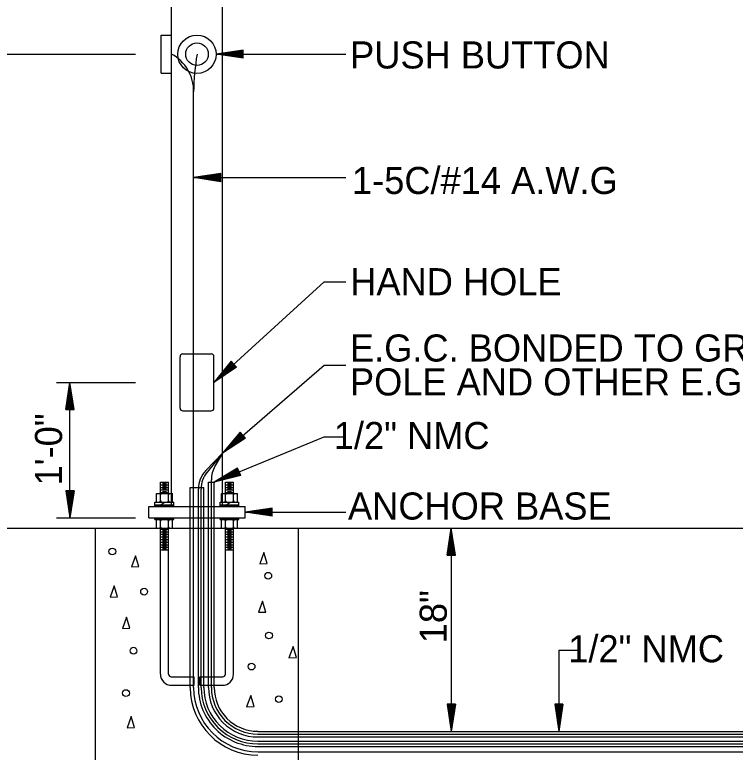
# Model space of a CAD drawing. Extents: x 1370140 to 1371141, y 380020 to 380660.
# Drawn here: x 1370273.3 to 1370406.3, y 380391.4 to 380527.5 of the extents above; entities that cross this region are included whole.
import ezdxf

# ---------------------------------------------------------------- set-up
doc = ezdxf.new("R2010")
doc.units = 0
doc.layers.add('R_Draft', color=7, linetype='Continuous')

msp = doc.modelspace()

# ---------------------------------------------------------------- linework, layer by layer
at = {"layer": 'R_Draft'}
for p, q in [((1370302.28, 380436.73), (1370302.28, 380532.73)), ((1370311.66, 380436.73), (1370311.66, 380532.73)), ((1370300.37, 380523.73), (1370302.28, 380523.73)), ((1370300.37, 380516.73), (1370300.37, 380523.73)), ((1370262.28, 380520.23), (1370295.6, 380520.23)), ((1370315.51, 380520.98), (1370310.51, 380520.23)), ((1370310.51, 380520.23), (1370334.45, 380520.23)), ((1370315.51, 380519.48), (1370310.51, 380520.23)), ((1370315.51, 380520.86), (1370311.35, 380520.23)), ((1370315.51, 380519.61), (1370311.35, 380520.23)), ((1370315.51, 380520.73), (1370312.21, 380520.23)), ((1370315.51, 380519.74), (1370312.21, 380520.23)), ((1370315.51, 380520.61), (1370313.04, 380520.23)), ((1370315.51, 380519.86), (1370313.04, 380520.23)), ((1370315.51, 380520.48), (1370313.89, 380520.23)), ((1370315.51, 380519.99), (1370313.89, 380520.23)), ((1370315.51, 380520.35), (1370314.72, 380520.23)), ((1370315.51, 380520.12), (1370314.72, 380520.23)), ((1370315.51, 380519.48), (1370315.51, 380520.98)), ((1370300.37, 380516.73), (1370302.28, 380516.73)), ((1370306.35, 380403.34), (1370306.35, 380513.28)), ((1370311.35, 380498.2), (1370306.35, 380497.45)), ((1370306.35, 380497.45), (1370334.45, 380497.45)), ((1370311.35, 380496.7), (1370306.35, 380497.45)), ((1370311.35, 380498.08), (1370307.19, 380497.45)), ((1370311.35, 380496.83), (1370307.19, 380497.45)), ((1370311.35, 380497.95), (1370308.05, 380497.45)), ((1370311.35, 380496.95), (1370308.05, 380497.45)), ((1370311.35, 380497.82), (1370308.88, 380497.45)), ((1370311.35, 380497.08), (1370308.88, 380497.45)), ((1370311.35, 380497.7), (1370309.73, 380497.45)), ((1370311.35, 380497.21), (1370309.73, 380497.45)), ((1370311.35, 380497.57), (1370310.56, 380497.45)), ((1370311.35, 380497.33), (1370310.56, 380497.45)), ((1370311.35, 380496.7), (1370311.35, 380498.2)), ((1370310.1, 380459.65), (1370330.44, 380478.2)), ((1370330.44, 380478.2), (1370334.45, 380478.2)), ((1370303.85, 380454.9), (1370303.85, 380464.4)), ((1370304.35, 380464.9), (1370309.6, 380464.9)), ((1370310.1, 380454.9), (1370310.1, 380464.4)), ((1370313.28, 380463.57), (1370310.1, 380459.65)), ((1370313.37, 380463.48), (1370310.71, 380460.21)), ((1370313.45, 380463.39), (1370311.35, 380460.79)), ((1370313.54, 380463.29), (1370311.96, 380461.35)), ((1370313.62, 380463.2), (1370312.59, 380461.92)), ((1370313.71, 380463.11), (1370313.2, 380462.49)), ((1370314.29, 380462.47), (1370313.28, 380463.57)), ((1370314.29, 380462.47), (1370310.1, 380459.65)), ((1370314.21, 380462.56), (1370310.71, 380460.21)), ((1370314.12, 380462.65), (1370311.35, 380460.79)), ((1370311.66, 380446.6), (1370330.44, 380462.85)), ((1370314.04, 380462.74), (1370311.96, 380461.35)), ((1370313.95, 380462.84), (1370312.59, 380461.92)), ((1370313.87, 380462.93), (1370313.2, 380462.49)), ((1370330.44, 380462.85), (1370334.45, 380462.85)), ((1370281.03, 380459.65), (1370295.6, 380459.65)), ((1370282.78, 380454.65), (1370283.53, 380459.65)), ((1370283.53, 380434.65), (1370283.53, 380459.65)), ((1370284.28, 380454.65), (1370283.53, 380459.65)), ((1370282.91, 380454.65), (1370283.53, 380458.81)), ((1370283.04, 380454.65), (1370283.53, 380457.95)), ((1370284.16, 380454.65), (1370283.53, 380458.81)), ((1370284.03, 380454.65), (1370283.53, 380457.95)), ((1370283.16, 380454.65), (1370283.53, 380457.12)), ((1370283.29, 380454.65), (1370283.53, 380456.27)), ((1370283.91, 380454.65), (1370283.53, 380457.12)), ((1370283.78, 380454.65), (1370283.53, 380456.27)), ((1370283.42, 380454.65), (1370283.53, 380455.44)), ((1370283.65, 380454.65), (1370283.53, 380455.44)), ((1370282.78, 380454.65), (1370284.28, 380454.65)), ((1370304.35, 380454.4), (1370309.6, 380454.4)), ((1370310.14, 380441.23), (1370330.44, 380449.6)), ((1370314.93, 380450.46), (1370311.66, 380446.6)), ((1370315.01, 380450.37), (1370312.29, 380447.15)), ((1370315.83, 380449.43), (1370312.29, 380447.15)), ((1370315.09, 380450.27), (1370312.93, 380447.72)), ((1370315.75, 380449.52), (1370312.93, 380447.72)), ((1370315.17, 380450.18), (1370313.56, 380448.27)), ((1370315.67, 380449.62), (1370313.56, 380448.27)), ((1370315.26, 380450.08), (1370314.2, 380448.83)), ((1370315.58, 380449.71), (1370314.2, 380448.83)), ((1370315.34, 380449.99), (1370314.83, 380449.38)), ((1370315.5, 380449.81), (1370314.83, 380449.38)), ((1370315.91, 380449.33), (1370314.93, 380450.46)), ((1370330.44, 380449.6), (1370334.45, 380449.6)), ((1370315.91, 380449.33), (1370311.66, 380446.6)), ((1370311.66, 380446.6), (1370308.61, 380443.4)), ((1370311.66, 380446.6), (1370308.83, 380443.09)), ((1370311.66, 380446.6), (1370310.27, 380444.16)), ((1370314.47, 380443.83), (1370310.14, 380441.23)), ((1370314.52, 380443.71), (1370310.91, 380441.55)), ((1370314.57, 380443.6), (1370311.7, 380441.87)), ((1370314.95, 380442.68), (1370311.7, 380441.87)), ((1370314.62, 380443.48), (1370312.47, 380442.19)), ((1370314.9, 380442.79), (1370312.47, 380442.19)), ((1370314.67, 380443.36), (1370313.26, 380442.52)), ((1370314.85, 380442.91), (1370313.26, 380442.52)), ((1370314.72, 380443.24), (1370314.03, 380442.83)), ((1370314.8, 380443.03), (1370314.03, 380442.83)), ((1370315.05, 380442.44), (1370314.47, 380443.83)), ((1370309.62, 380403.34), (1370309.62, 380441.69)), ((1370315.05, 380442.44), (1370310.14, 380441.23)), ((1370315, 380442.56), (1370310.91, 380441.55)), ((1370300.22, 380441.23), (1370301.72, 380441.23)), ((1370300.22, 380439.15), (1370300.22, 380441.23)), ((1370300.22, 380440.75), (1370301.72, 380440.75)), ((1370300.22, 380440.27), (1370301.72, 380440.27)), ((1370300.6, 380440.98), (1370301.35, 380440.98)), ((1370300.6, 380440.5), (1370301.35, 380440.5)), ((1370300.6, 380440.02), (1370301.35, 380440.02)), ((1370301.72, 380439.15), (1370301.72, 380441.23)), ((1370305.72, 380403.34), (1370305.72, 380440.27)), ((1370305.72, 380440.27), (1370308.22, 380440.27)), ((1370307.22, 380403.34), (1370307.22, 380439.95)), ((1370307.72, 380403.34), (1370307.72, 380439.95)), ((1370308.22, 380403.34), (1370308.22, 380440.27)), ((1370309.1, 380403.34), (1370309.1, 380441.23)), ((1370309.1, 380441.23), (1370310.14, 380441.23)), ((1370310.14, 380403.34), (1370310.14, 380441.23)), ((1370312.22, 380441.23), (1370313.72, 380441.23)), ((1370312.22, 380439.15), (1370312.22, 380441.23)), ((1370312.22, 380440.75), (1370313.72, 380440.75)), ((1370312.22, 380440.27), (1370313.72, 380440.27)), ((1370312.6, 380440.98), (1370313.35, 380440.98)), ((1370312.6, 380440.5), (1370313.35, 380440.5)), ((1370312.6, 380440.02), (1370313.35, 380440.02)), ((1370313.72, 380439.15), (1370313.72, 380441.23)), ((1370282.78, 380439.65), (1370283.53, 380434.65)), ((1370284.28, 380439.65), (1370282.78, 380439.65)), ((1370282.91, 380439.65), (1370283.53, 380435.48)), ((1370283.04, 380439.65), (1370283.53, 380436.34)), ((1370283.16, 380439.65), (1370283.53, 380437.17)), ((1370283.29, 380439.65), (1370283.53, 380438.02)), ((1370283.42, 380439.65), (1370283.53, 380438.86)), ((1370284.28, 380439.65), (1370283.53, 380434.65)), ((1370283.78, 380439.65), (1370283.53, 380438.02)), ((1370284.03, 380439.65), (1370283.53, 380436.34)), ((1370284.16, 380439.65), (1370283.53, 380435.48)), ((1370283.91, 380439.65), (1370283.53, 380437.17)), ((1370283.65, 380439.65), (1370283.53, 380438.86)), ((1370299.47, 380437.57), (1370299.47, 380439.15)), ((1370299.47, 380439.15), (1370302.47, 380439.15)), ((1370300.22, 380439.79), (1370301.72, 380439.79)), ((1370300.22, 380439.31), (1370301.72, 380439.31)), ((1370300.22, 380437.57), (1370300.22, 380439.15)), ((1370300.6, 380439.54), (1370301.35, 380439.54)), ((1370301.72, 380437.57), (1370301.72, 380439.15)), ((1370302.47, 380437.57), (1370302.47, 380439.15)), ((1370311.47, 380437.57), (1370311.47, 380439.15)), ((1370311.47, 380439.15), (1370314.47, 380439.15)), ((1370312.22, 380439.79), (1370313.72, 380439.79)), ((1370312.22, 380439.31), (1370313.72, 380439.31)), ((1370312.22, 380437.57), (1370312.22, 380439.15)), ((1370312.6, 380439.54), (1370313.35, 380439.54)), ((1370313.72, 380437.57), (1370313.72, 380439.15)), ((1370314.47, 380437.57), (1370314.47, 380439.15)), ((1370299.22, 380436.73), (1370299.22, 380437.57)), ((1370299.22, 380437.57), (1370302.72, 380437.57)), ((1370300.22, 380437.06), (1370301.1, 380437.55)), ((1370302.72, 380436.73), (1370302.72, 380437.57)), ((1370311.22, 380436.73), (1370311.22, 380437.57)), ((1370311.22, 380437.57), (1370314.72, 380437.57)), ((1370312.37, 380437.06), (1370313.19, 380437.56)), ((1370314.72, 380436.73), (1370314.72, 380437.57)), ((1370298.1, 380434.65), (1370298.1, 380436.73)), ((1370298.1, 380436.73), (1370315.85, 380436.73)), ((1370299.22, 380437.06), (1370302.72, 380437.06)), ((1370299.22, 380436.89), (1370299.4, 380437.06)), ((1370299.24, 380436.73), (1370299.57, 380437.06)), ((1370299.42, 380436.73), (1370299.75, 380437.06)), ((1370299.59, 380436.73), (1370299.93, 380437.06)), ((1370299.77, 380436.73), (1370300.1, 380437.06)), ((1370299.95, 380436.73), (1370300.22, 380437.01)), ((1370300.12, 380436.73), (1370300.22, 380436.83)), ((1370300.22, 380436.81), (1370300.48, 380437.06)), ((1370300.22, 380436.98), (1370300.3, 380437.06)), ((1370300.32, 380436.73), (1370300.66, 380437.06)), ((1370300.5, 380436.73), (1370300.83, 380437.06)), ((1370300.68, 380436.73), (1370301.01, 380437.06)), ((1370300.85, 380436.73), (1370301.19, 380437.06)), ((1370301.03, 380436.73), (1370301.36, 380437.06)), ((1370301.21, 380436.73), (1370301.54, 380437.06)), ((1370301.38, 380436.73), (1370301.72, 380437.06)), ((1370301.56, 380436.73), (1370301.72, 380436.89)), ((1370301.72, 380436.85), (1370301.93, 380437.06)), ((1370301.72, 380437.03), (1370301.75, 380437.06)), ((1370301.77, 380436.73), (1370302.11, 380437.06)), ((1370301.95, 380436.73), (1370302.28, 380437.06)), ((1370302.13, 380436.73), (1370302.28, 380436.89)), ((1370302.28, 380436.75), (1370302.6, 380437.06)), ((1370302.28, 380436.92), (1370302.42, 380437.06)), ((1370302.44, 380436.73), (1370302.72, 380437.01)), ((1370302.62, 380436.73), (1370302.72, 380436.83)), ((1370311.22, 380437.06), (1370314.72, 380437.06)), ((1370311.26, 380436.73), (1370311.59, 380437.06)), ((1370311.28, 380436.93), (1370311.41, 380437.06)), ((1370311.43, 380436.73), (1370311.66, 380436.95)), ((1370311.61, 380436.73), (1370311.66, 380436.78)), ((1370311.66, 380436.83), (1370311.89, 380437.06)), ((1370311.66, 380437.01), (1370311.71, 380437.06)), ((1370311.73, 380436.73), (1370312.07, 380437.06)), ((1370311.91, 380436.73), (1370312.22, 380437.04)), ((1370312.09, 380436.73), (1370312.22, 380436.86)), ((1370312.22, 380436.82), (1370312.47, 380437.06)), ((1370312.22, 380436.99), (1370312.29, 380437.06)), ((1370312.31, 380436.73), (1370312.64, 380437.06)), ((1370312.49, 380436.73), (1370312.82, 380437.06)), ((1370312.66, 380436.73), (1370313, 380437.06)), ((1370312.84, 380436.73), (1370313.17, 380437.06)), ((1370313.02, 380436.73), (1370313.35, 380437.06)), ((1370313.19, 380436.73), (1370313.53, 380437.06)), ((1370313.37, 380436.73), (1370313.7, 380437.06)), ((1370313.55, 380436.73), (1370313.72, 380436.9)), ((1370313.72, 380436.87), (1370313.91, 380437.06)), ((1370313.72, 380437.05), (1370313.73, 380437.06)), ((1370313.75, 380436.73), (1370314.09, 380437.06)), ((1370313.93, 380436.73), (1370314.26, 380437.06)), ((1370314.11, 380436.73), (1370314.44, 380437.06)), ((1370314.28, 380436.73), (1370314.62, 380437.06)), ((1370314.46, 380436.73), (1370314.66, 380436.93)), ((1370314.64, 380436.73), (1370314.7, 380436.79)), ((1370315.85, 380434.65), (1370315.85, 380436.73)), ((1370320.85, 380436.44), (1370315.85, 380435.69)), ((1370320.85, 380436.31), (1370316.68, 380435.69)), ((1370320.85, 380436.19), (1370317.54, 380435.69)), ((1370320.85, 380436.06), (1370318.37, 380435.69)), ((1370320.85, 380435.93), (1370319.22, 380435.69)), ((1370320.85, 380435.81), (1370320.06, 380435.69)), ((1370320.85, 380434.94), (1370320.85, 380436.44)), ((1370281.03, 380434.65), (1370295.6, 380434.65)), ((1370298.1, 380434.65), (1370315.85, 380434.65)), ((1370299.22, 380434.31), (1370299.22, 380434.65)), ((1370299.22, 380434.48), (1370299.39, 380434.65)), ((1370299.23, 380434.31), (1370299.57, 380434.65)), ((1370299.41, 380434.31), (1370299.74, 380434.65)), ((1370299.59, 380434.31), (1370299.92, 380434.65)), ((1370299.76, 380434.31), (1370300.1, 380434.65)), ((1370299.94, 380434.31), (1370300.22, 380434.6)), ((1370300.22, 380434.39), (1370300.48, 380434.65)), ((1370300.22, 380434.57), (1370300.3, 380434.65)), ((1370300.32, 380434.31), (1370300.66, 380434.65)), ((1370300.5, 380434.31), (1370300.83, 380434.65)), ((1370300.68, 380434.31), (1370301.01, 380434.65)), ((1370300.85, 380434.31), (1370301.19, 380434.65)), ((1370301.03, 380434.31), (1370301.36, 380434.65)), ((1370301.21, 380434.31), (1370301.54, 380434.65)), ((1370301.38, 380434.31), (1370301.72, 380434.65)), ((1370301.56, 380434.31), (1370301.72, 380434.48)), ((1370301.72, 380434.31), (1370302.05, 380434.65)), ((1370301.72, 380434.49), (1370301.88, 380434.65)), ((1370301.9, 380434.31), (1370302.23, 380434.65)), ((1370302.07, 380434.31), (1370302.41, 380434.65)), ((1370302.25, 380434.31), (1370302.58, 380434.65)), ((1370302.43, 380434.31), (1370302.72, 380434.61)), ((1370302.6, 380434.31), (1370302.72, 380434.43)), ((1370302.72, 380434.31), (1370302.72, 380434.65)), ((1370311.22, 380434.31), (1370311.22, 380434.65)), ((1370311.23, 380434.64), (1370311.24, 380434.65)), ((1370311.3, 380434.54), (1370311.41, 380434.65)), ((1370311.38, 380434.44), (1370311.59, 380434.65)), ((1370311.46, 380434.33), (1370311.77, 380434.65)), ((1370311.61, 380434.31), (1370311.94, 380434.65)), ((1370311.79, 380434.31), (1370312.12, 380434.65)), ((1370311.96, 380434.31), (1370312.22, 380434.57)), ((1370312.22, 380434.38), (1370312.49, 380434.65)), ((1370312.22, 380434.56), (1370312.31, 380434.65)), ((1370312.33, 380434.31), (1370312.66, 380434.65)), ((1370312.51, 380434.31), (1370312.84, 380434.65)), ((1370312.68, 380434.31), (1370313.02, 380434.65)), ((1370312.86, 380434.31), (1370313.19, 380434.65)), ((1370313.04, 380434.31), (1370313.37, 380434.65)), ((1370313.21, 380434.31), (1370313.55, 380434.65)), ((1370313.39, 380434.31), (1370313.72, 380434.64)), ((1370313.57, 380434.31), (1370313.72, 380434.47)), ((1370313.72, 380434.47), (1370313.9, 380434.65)), ((1370313.72, 380434.64), (1370313.72, 380434.65)), ((1370313.74, 380434.31), (1370314.08, 380434.65)), ((1370313.92, 380434.31), (1370314.26, 380434.65)), ((1370314.1, 380434.31), (1370314.43, 380434.65)), ((1370314.28, 380434.31), (1370314.61, 380434.65)), ((1370314.72, 380434.31), (1370314.72, 380434.65)), ((1370315.85, 380435.69), (1370334.45, 380435.69)), ((1370320.85, 380434.94), (1370315.85, 380435.69)), ((1370320.85, 380435.06), (1370316.68, 380435.69)), ((1370320.85, 380435.19), (1370317.54, 380435.69)), ((1370320.85, 380435.32), (1370318.37, 380435.69)), ((1370320.85, 380435.45), (1370319.22, 380435.69)), ((1370320.85, 380435.57), (1370320.06, 380435.69)), ((1370299.22, 380434.31), (1370302.72, 380434.31)), ((1370299.47, 380432.73), (1370299.47, 380434.31)), ((1370300.12, 380434.31), (1370300.22, 380434.42)), ((1370300.22, 380432.73), (1370300.22, 380434.31)), ((1370301.72, 380432.73), (1370301.72, 380434.31)), ((1370302.47, 380432.73), (1370302.47, 380434.31)), ((1370311.22, 380434.31), (1370314.72, 380434.31)), ((1370311.47, 380432.73), (1370311.47, 380434.31)), ((1370312.14, 380434.31), (1370312.22, 380434.39)), ((1370312.22, 380432.73), (1370312.22, 380434.31)), ((1370313.72, 380432.73), (1370313.72, 380434.31)), ((1370314.45, 380434.31), (1370314.53, 380434.39)), ((1370314.47, 380432.73), (1370314.47, 380434.31)), ((1370221.8, 380432.73), (1370486.02, 380432.73)), ((1370288.22, 380357.73), (1370288.22, 380432.73)), ((1370288.22, 380432.73), (1370325.72, 380432.73)), ((1370299.47, 380432.73), (1370302.47, 380432.73)), ((1370300.22, 380405.81), (1370300.22, 380432.73)), ((1370300.22, 380432.57), (1370301.72, 380432.57)), ((1370300.22, 380432.09), (1370301.72, 380432.09)), ((1370300.6, 380432.32), (1370301.35, 380432.32)), ((1370300.6, 380431.84), (1370301.35, 380431.84)), ((1370301.72, 380405.79), (1370301.72, 380432.73)), ((1370311.47, 380432.73), (1370314.47, 380432.73)), ((1370312.22, 380405.79), (1370312.22, 380432.73)), ((1370312.22, 380432.57), (1370313.72, 380432.57)), ((1370312.22, 380432.09), (1370313.72, 380432.09)), ((1370312.6, 380432.32), (1370313.35, 380432.32)), ((1370312.6, 380431.84), (1370313.35, 380431.84)), ((1370313.72, 380405.81), (1370313.72, 380432.73)), ((1370325.72, 380357.73), (1370325.72, 380432.73)), ((1370353.16, 380427.73), (1370353.91, 380432.73)), ((1370353.29, 380427.73), (1370353.91, 380431.9)), ((1370353.91, 380432.73), (1370353.91, 380395.23)), ((1370354.66, 380427.73), (1370353.91, 380432.73)), ((1370354.54, 380427.73), (1370353.91, 380431.9)), ((1370300.22, 380431.61), (1370301.72, 380431.61)), ((1370300.22, 380431.13), (1370301.72, 380431.13)), ((1370300.22, 380430.65), (1370301.72, 380430.65)), ((1370300.6, 380431.36), (1370301.35, 380431.36)), ((1370300.6, 380430.88), (1370301.35, 380430.88)), ((1370300.6, 380430.4), (1370301.35, 380430.4)), ((1370312.22, 380431.61), (1370313.72, 380431.61)), ((1370312.22, 380431.13), (1370313.72, 380431.13)), ((1370312.22, 380430.65), (1370313.72, 380430.65)), ((1370312.6, 380431.36), (1370313.35, 380431.36)), ((1370312.6, 380430.88), (1370313.35, 380430.88)), ((1370312.6, 380430.4), (1370313.35, 380430.4)), ((1370353.41, 380427.73), (1370353.91, 380431.04)), ((1370354.41, 380427.73), (1370353.91, 380431.04)), ((1370300.22, 380430.17), (1370301.72, 380430.17)), ((1370300.22, 380429.69), (1370301.72, 380429.69)), ((1370300.22, 380429.21), (1370301.72, 380429.21)), ((1370300.6, 380429.92), (1370301.35, 380429.92)), ((1370300.6, 380429.44), (1370301.35, 380429.44)), ((1370312.22, 380430.17), (1370313.72, 380430.17)), ((1370312.22, 380429.69), (1370313.72, 380429.69)), ((1370312.22, 380429.21), (1370313.72, 380429.21)), ((1370312.6, 380429.92), (1370313.35, 380429.92)), ((1370312.6, 380429.44), (1370313.35, 380429.44)), ((1370353.54, 380427.73), (1370353.91, 380430.21)), ((1370353.67, 380427.73), (1370353.91, 380429.36)), ((1370354.28, 380427.73), (1370353.91, 380430.21)), ((1370354.16, 380427.73), (1370353.91, 380429.36)), ((1370300.22, 380428.73), (1370301.72, 380428.73)), ((1370300.6, 380428.96), (1370301.35, 380428.96)), ((1370312.22, 380428.73), (1370313.72, 380428.73)), ((1370312.6, 380428.96), (1370313.35, 380428.96)), ((1370353.16, 380427.73), (1370354.66, 380427.73)), ((1370353.79, 380427.73), (1370353.91, 380428.52)), ((1370354.03, 380427.73), (1370353.91, 380428.52)), ((1370373.75, 380410.24), (1370373.75, 380395.23)), ((1370373.75, 380410.24), (1370377.72, 380410.24)), ((1370302.22, 380405.29), (1370306.47, 380405.29)), ((1370306.47, 380403.73), (1370306.47, 380405.29)), ((1370307.47, 380403.73), (1370307.47, 380405.29)), ((1370307.47, 380405.29), (1370311.72, 380405.29)), ((1370302.3, 380403.73), (1370306.47, 380403.73)), ((1370307.47, 380403.73), (1370311.64, 380403.73)), ((1370353.16, 380400.23), (1370353.91, 380395.23)), ((1370354.66, 380400.23), (1370353.16, 380400.23)), ((1370353.29, 380400.23), (1370353.91, 380396.07)), ((1370353.41, 380400.23), (1370353.91, 380396.93)), ((1370353.54, 380400.23), (1370353.91, 380397.76)), ((1370353.67, 380400.23), (1370353.91, 380398.61)), ((1370353.79, 380400.23), (1370353.91, 380399.44)), ((1370354.66, 380400.23), (1370353.91, 380395.23)), ((1370354.15, 380400.23), (1370353.91, 380398.61)), ((1370354.41, 380400.23), (1370353.91, 380396.93)), ((1370354.54, 380400.23), (1370353.91, 380396.07)), ((1370354.28, 380400.23), (1370353.91, 380397.76)), ((1370354.03, 380400.23), (1370353.91, 380399.44)), ((1370373, 380400.23), (1370373.75, 380395.23)), ((1370374.5, 380400.23), (1370373, 380400.23)), ((1370373.13, 380400.23), (1370373.75, 380396.07)), ((1370373.25, 380400.23), (1370373.75, 380396.93)), ((1370373.38, 380400.23), (1370373.75, 380397.76)), ((1370373.51, 380400.23), (1370373.75, 380398.61)), ((1370373.63, 380400.23), (1370373.75, 380399.44)), ((1370374.5, 380400.23), (1370373.75, 380395.23)), ((1370373.99, 380400.23), (1370373.75, 380398.61)), ((1370374.25, 380400.23), (1370373.75, 380396.93)), ((1370374.38, 380400.23), (1370373.75, 380396.07)), ((1370374.12, 380400.23), (1370373.75, 380397.76)), ((1370373.87, 380400.23), (1370373.75, 380399.44)), ((1370318.22, 380395.23), (1370441.9, 380395.23)), ((1370318.22, 380394.71), (1370440.66, 380394.71)), ((1370318.22, 380394.19), (1370441.9, 380394.19)), ((1370318.22, 380393.44), (1370441.9, 380393.44)), ((1370318.22, 380392.94), (1370448.83, 380392.94)), ((1370318.22, 380392.44), (1370445.2, 380392.44)), ((1370318.22, 380391.46), (1370441.9, 380391.46))]:
    msp.add_line(p, q, dxfattribs=at)
for points in [[(1370295.61, 380427.66), (1370294.86, 380425.59), (1370296.23, 380425.65), (1370295.61, 380427.66)], [(1370319.33, 380428.23), (1370318.57, 380426.15), (1370319.94, 380426.21), (1370319.33, 380428.23)], [(1370291.7, 380422.08), (1370290.95, 380420), (1370292.32, 380420.06), (1370291.7, 380422.08)], [(1370319.08, 380419.28), (1370318.32, 380417.21), (1370319.7, 380417.26), (1370319.08, 380419.28)], [(1370293.98, 380416.28), (1370293.22, 380414.21), (1370294.59, 380414.26), (1370293.98, 380416.28)], [(1370324.7, 380410.87), (1370323.95, 380408.79), (1370325.32, 380408.85), (1370324.7, 380410.87)], [(1370316.88, 380401.82), (1370316.13, 380399.74), (1370317.5, 380399.8), (1370316.88, 380401.82)], [(1370294.81, 380397.98), (1370294.06, 380395.9), (1370295.43, 380395.96), (1370294.81, 380397.98)]]:
    msp.add_lwpolyline(points, dxfattribs=at)
for centre, radius in [((1370306.97, 380520.23), 3.54), ((1370306.97, 380520.23), 2.08), ((1370291.34, 380428.43), 0.625), ((1370320.12, 380423.96), 0.625), ((1370297.21, 380421.02), 0.625), ((1370320.26, 380412.92), 0.625), ((1370295.26, 380410.12), 0.625), ((1370317.04, 380407.19), 0.625), ((1370293.86, 380402.3), 0.625), ((1370322.07, 380401.18), 0.625)]:
    msp.add_circle(centre, radius, dxfattribs=at)
for centre, radius, start, end in [((1370298.68, 380513.47), 7.67, 358.6476, 61.9685), ((1370355.93, 380512.33), 49.59, 170.8268, 178.8957), ((1370304.35, 380464.4), 0.5, 90, 180), ((1370309.6, 380464.4), 0.5, 360, 90), ((1370304.35, 380454.9), 0.5, 180, 270), ((1370309.6, 380454.9), 0.5, 270, 0), ((1370314.62, 380441.69), 5, 150.4069, 180), ((1370312.22, 380439.95), 5, 136.323, 180), ((1370312.72, 380439.95), 5, 141.118, 180), ((1370299.97, 380438.9), 0.25, 0, 90), ((1370300.47, 380438.9), 0.25, 90, 180), ((1370301.47, 380438.9), 0.25, 0, 90), ((1370301.97, 380438.9), 0.25, 90, 180), ((1370311.97, 380438.9), 0.25, 0, 90), ((1370312.47, 380438.9), 0.25, 90, 180), ((1370313.47, 380438.9), 0.25, 0, 90), ((1370313.97, 380438.9), 0.25, 90, 180), ((1370299.97, 380437.82), 0.25, 270, 0), ((1370300.47, 380437.82), 0.25, 180, 270), ((1370301.47, 380437.82), 0.25, 270, 0), ((1370301.97, 380437.82), 0.25, 180, 270), ((1370311.97, 380437.82), 0.25, 270, 0), ((1370312.47, 380437.82), 0.25, 180, 270), ((1370313.47, 380437.82), 0.25, 270, 0), ((1370313.97, 380437.82), 0.25, 180, 270), ((1370299.97, 380434.06), 0.25, 0, 90), ((1370300.47, 380434.06), 0.25, 90, 180), ((1370301.47, 380434.06), 0.25, 0, 90), ((1370301.97, 380434.06), 0.25, 90, 180), ((1370311.97, 380434.06), 0.25, 0, 90), ((1370312.47, 380434.06), 0.25, 90, 180), ((1370313.47, 380434.06), 0.25, 0, 90), ((1370313.97, 380434.06), 0.25, 90, 180), ((1370299.97, 380432.98), 0.25, 270, 0), ((1370300.47, 380432.98), 0.25, 180, 270), ((1370301.47, 380432.98), 0.25, 270, 0), ((1370301.97, 380432.98), 0.25, 180, 270), ((1370311.97, 380432.98), 0.25, 270, 0), ((1370312.47, 380432.98), 0.25, 180, 270), ((1370313.47, 380432.98), 0.25, 270, 0), ((1370313.97, 380432.98), 0.25, 180, 270), ((1370302.3, 380405.81), 2.08, 180, 270), ((1370302.22, 380405.79), 0.5, 180, 270), ((1370311.64, 380405.81), 2.08, 270, 0), ((1370311.72, 380405.79), 0.5, 270, 0), ((1370318.22, 380403.34), 12.5, 180, 270), ((1370318.22, 380403.34), 11.87, 180, 270), ((1370318.17, 380403.39), 10.95, 180.3, 270.3), ((1370318.17, 380403.39), 10.45, 180.3, 270.3), ((1370318.17, 380403.39), 9.95, 180.3, 270.3), ((1370318.23, 380403.33), 9.14, 179.9347, 269.9347), ((1370318.23, 380403.33), 8.61, 179.9263, 269.9263), ((1370318.23, 380403.33), 8.09, 179.9263, 269.9263)]:
    msp.add_arc(centre, radius, start, end, dxfattribs=at)

# ---------------------------------------------------------------- texts
for s, p in [('PUSH BUTTON', (1370335.23, 380517.6)), ('1-5C/#14 A.W.G', (1370335.58, 380494.43)), ('HAND HOLE', (1370335.26, 380475.74)), ('E.G.C. BONDED TO GROUND LUG ON ', (1370335.2, 380463.5)), ('POLE AND OTHER E.G.C. CONDUCTORS', (1370335.2, 380457.24)), (' 1/2" NMC ', (1370330.36, 380447.34)), ('ANCHOR BASE', (1370334.84, 380434.33)), (' 1/2" NMC ', (1370373.63, 380407.98))]:
    msp.add_text(s, height=5, dxfattribs=at).set_placement(p)
for s, p in [('1\'-0"', (1370282.07, 380440.62)), ('18"', (1370353.07, 380411.49))]:
    msp.add_text(s, height=5, rotation=90, dxfattribs=at).set_placement(p)

doc.saveas('drawing.dxf')
